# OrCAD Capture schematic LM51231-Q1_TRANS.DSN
size Custom
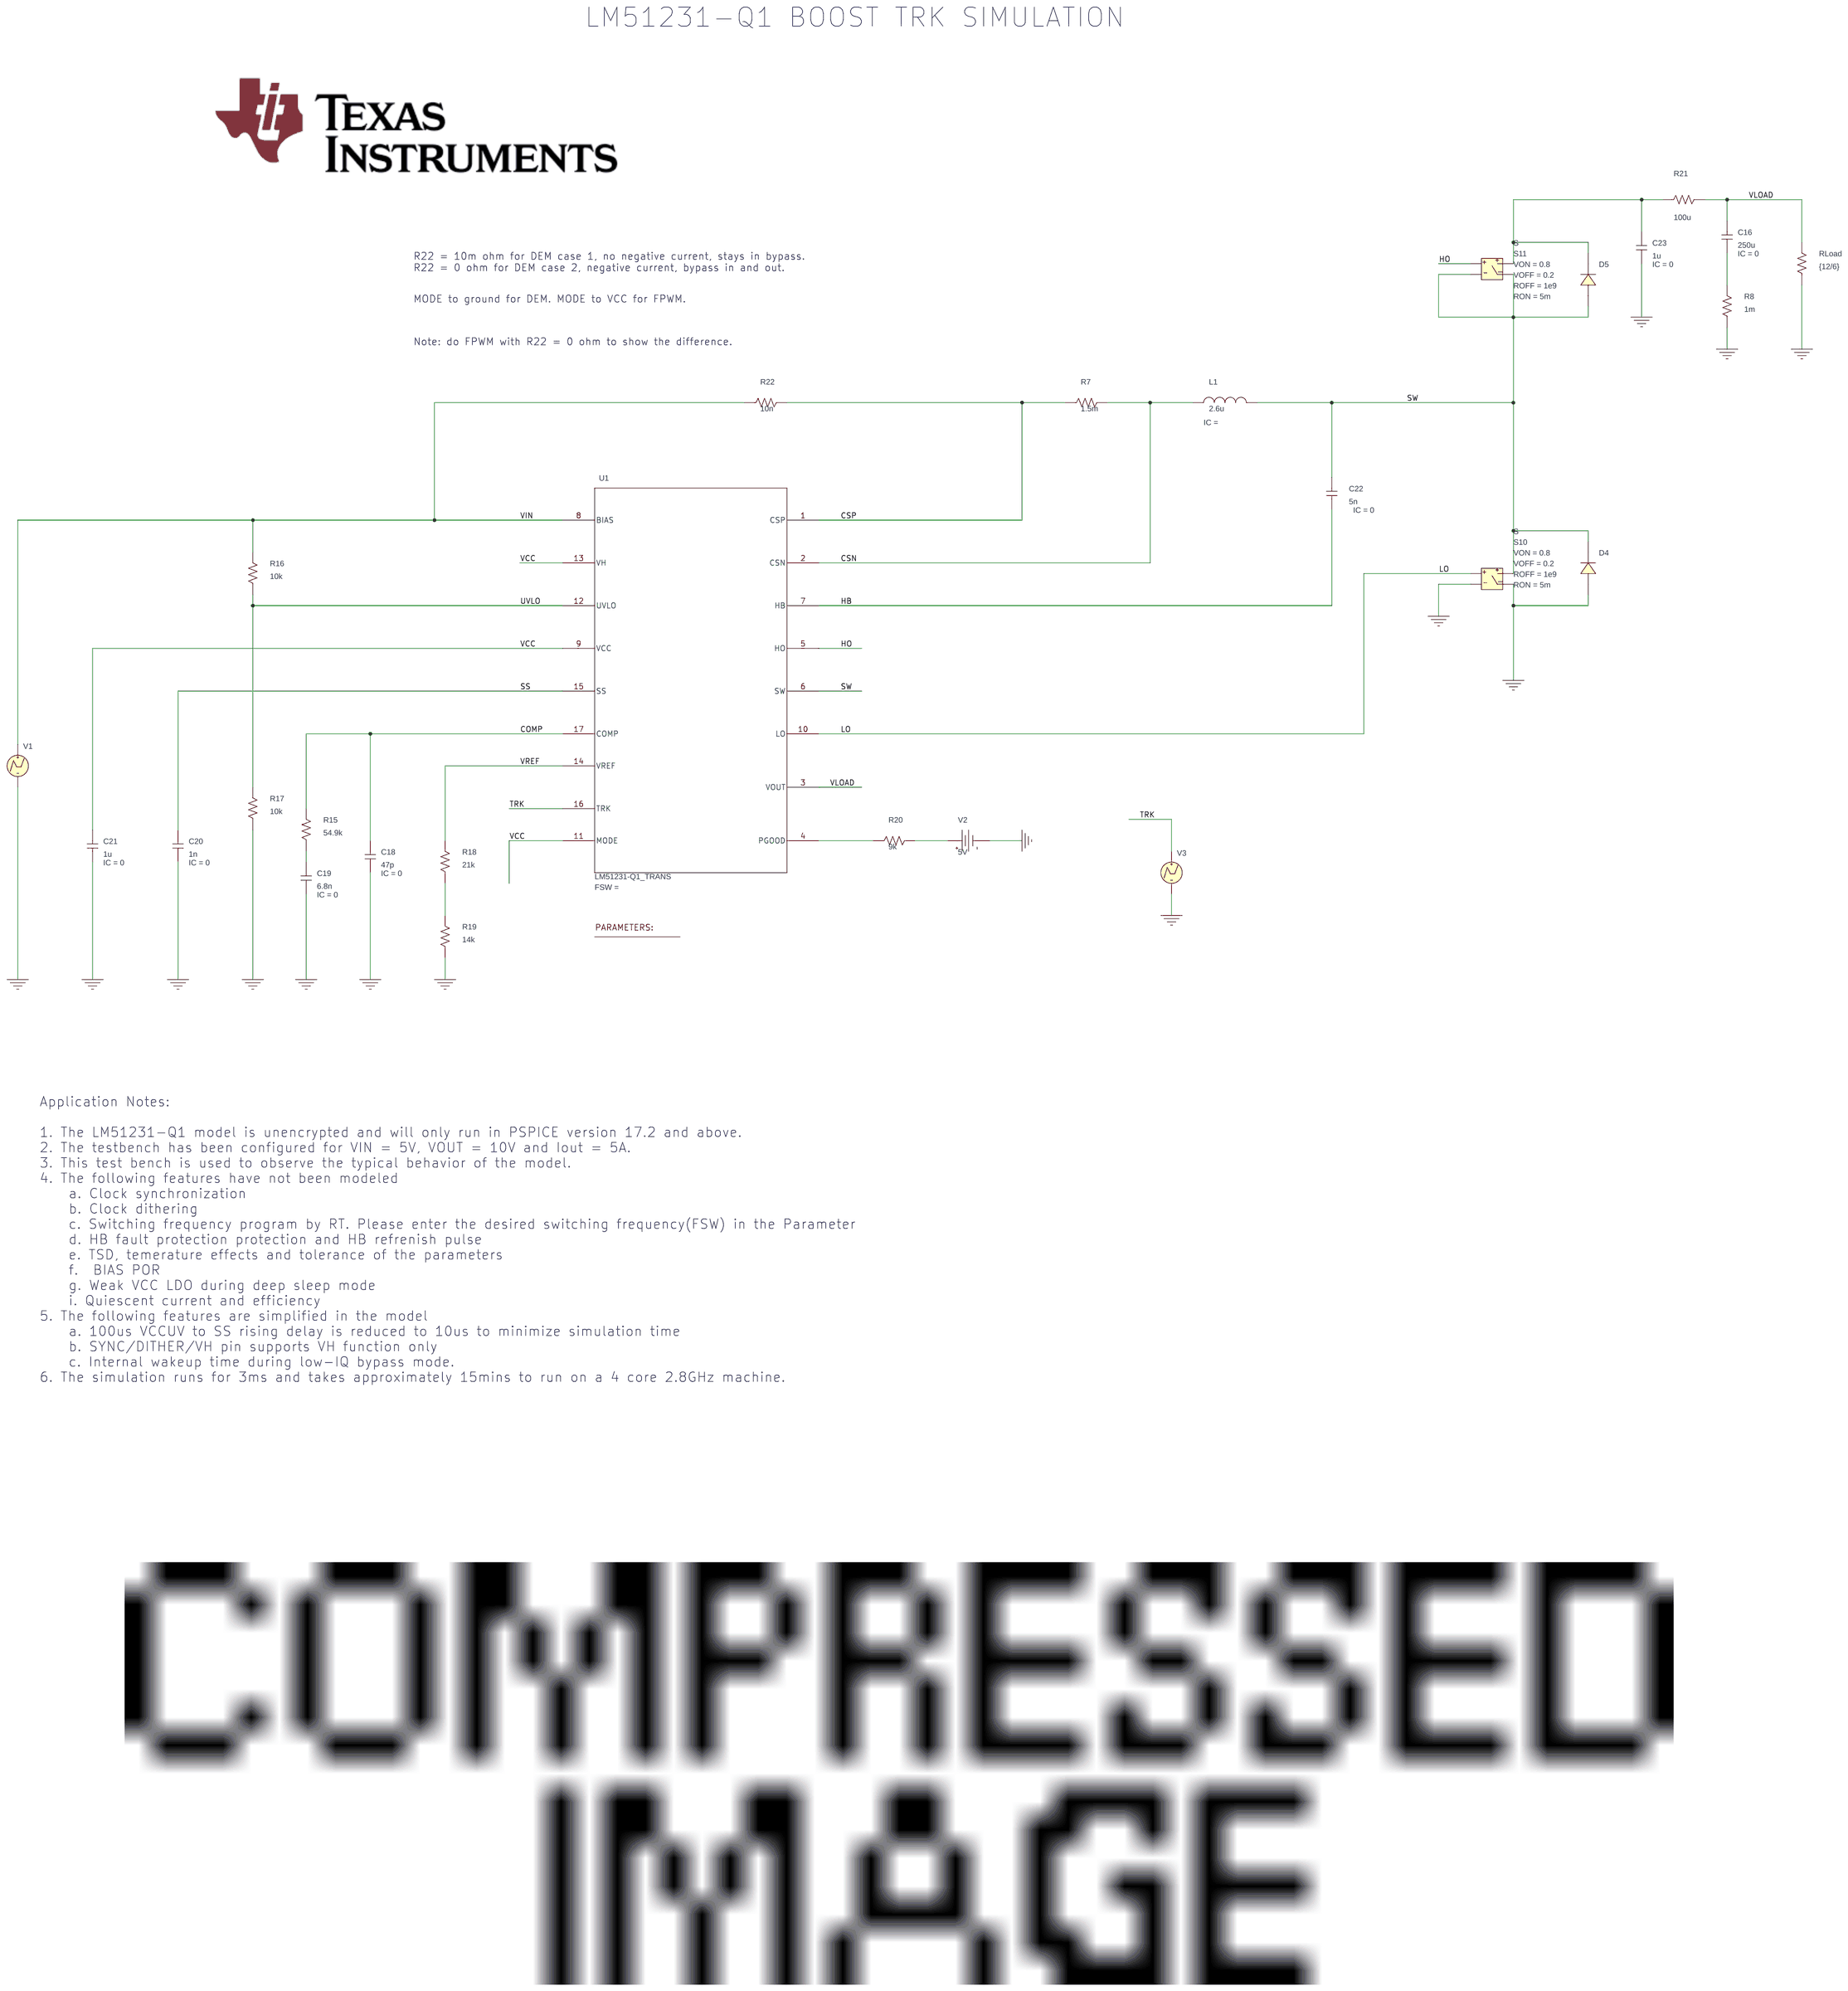
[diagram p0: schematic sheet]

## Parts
1  PARAM
C16  250u  [RAD/CK05]
C18  47p  [RAD/CK05]
C19  6.8n  [RAD/CK05]
C20  1n  [RAD/CK05]
C21  1u  [RAD/CK05]
C22  5n  [RAD/CK05]
C23  1u  [RAD/CK05]
D4  D_D1
D5  D_D1
L1  2.6u  [DISC/.350x.175/LS.200x.100/.034]
R7  1.5m  [AX/RC05]
R8  1m  [AX/RC05]
R15  54.9k  [AX/RC05]
R16  10k  [AX/RC05]
R17  10k  [AX/RC05]
R18  21k  [AX/RC05]
R19  14k  [AX/RC05]
R20  9k  [AX/RC05]
R21  100u  [AX/RC05]
R22  10n  [AX/RC05]
RLoad  {12/6}  [AX/RC05]
S10  S
S11  S
U1  LM51231-Q1_TRANS
V1  VPWL
V2  VDC
V3  VPWL

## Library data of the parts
1 = PARAM: FSW: 440k
C16 C18-C23 = C: IC: 0
D4 D5 = D_D1
L1 = L
R7 R8 R15-R22 RLoad = R
S10 S11 = S: ROFF: 1e9; RON: 5m; VOFF: 0.2; VON: 0.8
U1 = LM51231-Q1_TRANS
V1 = VPWL: T1: 0; T2: 50u; T3: 1m; V1: 0; V2: 13; V3: 13
V2 = VDC: DC: 5V
V3 = VPWL: T1: 0; T2: 0.4m; T3: 0.41m; T4: 0.5m; T5: 1.5m; T6: 1.6m; T7: 2m; V1: 0.4; V2: 0.4; V3: 0.17; V4: 0.17; V5: 0.17; V6: 0.4; V7: 0.4

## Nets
VCC: C21.2 U1.9(VCC) U1.11(MODE) U1.13(VH)
VIN: R16.2 R22.1 U1.8(BIAS) V1.1(+)
0: C18.1 C19.1 C20.1 C21.1 C23.1 D4.2(A) R8.1 R17.1 R19.1 RLoad.1 S10.1(2) S10.3(4) V1.2(-) V2.1(-) V3.2(-)
COMP: C18.2 R15.2 U1.17(COMP)
CSN: L1.1 R7.2 U1.2(CSN)
CSP: R7.1 R22.2 U1.1(CSP)
HB: C22.1 U1.7(HB)
HO: S11.0(1) U1.5(HO)
LO: S10.0(1) U1.10(LO)
SS: C20.2 U1.15(SS)
SW: C22.2 D4.1(C) D5.2(A) L1.2 S10.2(3) S11.1(2) S11.3(4) U1.6(SW)
TRK: U1.16(TRK) V3.1(+)
UVLO: R16.1 R17.2 U1.12(UVLO)
VLOAD: C16.2 R21.1 RLoad.2 U1.3(VOUT)
VREF: R18.2 U1.14(VREF)
N04526: C23.2 D5.1(C) R21.2 S11.2(3)
N04654: C16.1 R8.2
N05478: R20.1 U1.4(PGOOD)
N05484: R20.2 V2.0(+)
N05496: C19.2 R15.1
N05596: R18.1 R19.2

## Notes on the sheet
- LM51231-Q1 BOOST TRK SIMULATION
- R22 = 10m ohm for DEM case 1, no negative current, stays in bypass.
  R22 = 0 ohm for DEM case 2, negative current, bypass in and out.
- MODE to ground for DEM. MODE to VCC for FPWM.
- Note: do FPWM with R22 = 0 ohm to show the difference.
- Application Notes:
  1. The LM51231-Q1 model is unencrypted and will only run in PSPICE version 17.2 and above.
  2. The testbench has been configured for VIN = 5V, VOUT = 10V and Iout = 5A.
  3. This test bench is used to observe the typical behavior of the model.
  4. The following features have not been modeled
      a. Clock synchronization
      b. Clock dithering
      c. Switching frequency program by RT. Please enter the desired switching frequency(FSW) in the Parameter
      d. HB fault protection protection and HB refrenish pulse
      e. TSD, temerature effects and tolerance of the parameters
      f.  BIAS POR
      g. Weak VCC LDO during deep sleep mode
      i. Quiescent current and efficiency
  5. The following features are simplified in the model
      a. 100us VCCUV to SS rising delay is reduced to 10us to minimize simulation time
      b. SYNC/DITHER/VH pin supports VH function only
      c. Internal wakeup time during low-IQ bypass mode.
  6. The simulation runs for 3ms and takes approximately 15mins to run on a 4 core 2.8GHz machine.
